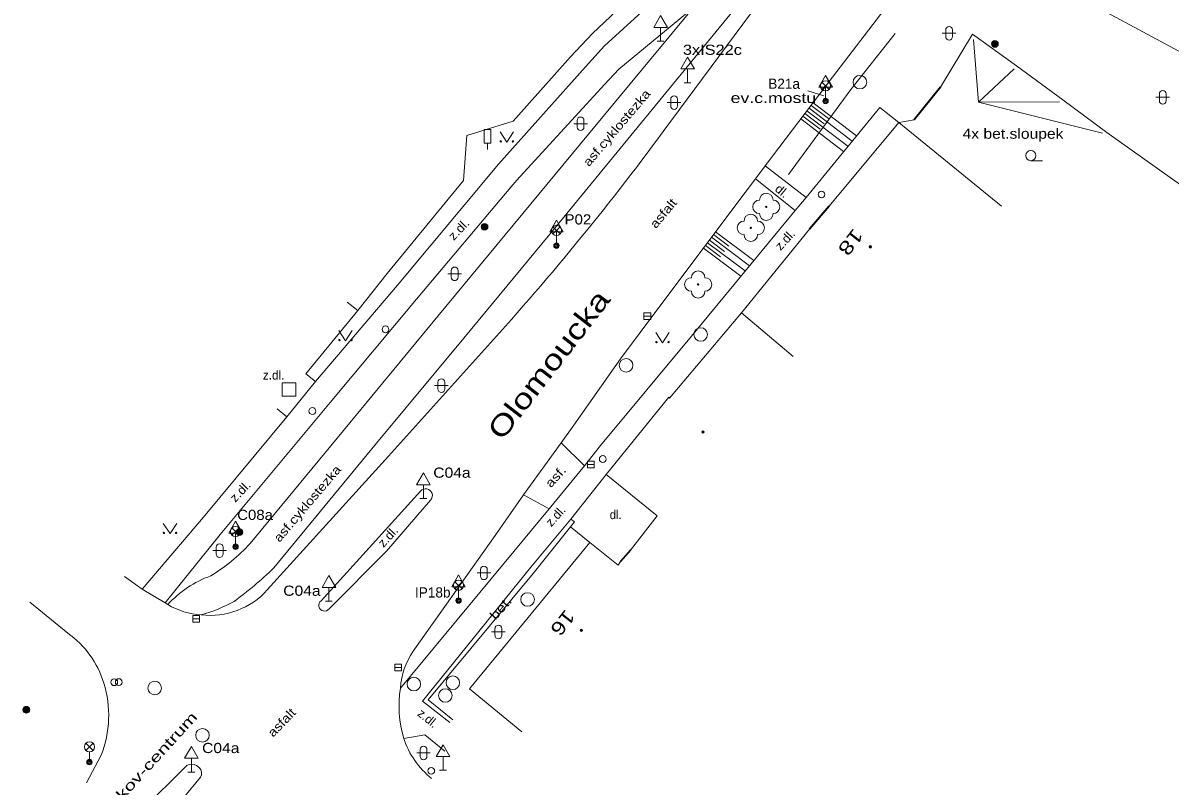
# Model space of a CAD drawing. Extents: x -568501 to -568291, y -1154101 to -1153799.
# Drawn here: x -568486.5 to -568402, y -1153998.8 to -1153942.5 of the extents above; entities that cross this region are included whole.
import ezdxf
from ezdxf.enums import TextEntityAlignment as Align

# ---------------------------------------------------------------- set-up
doc = ezdxf.new("R2010")
doc.units = 0
doc.header["$LTSCALE"] = 0.3
for name, color, linetype, lineweight in [('10', 7, 'Continuous', 13), ('11', 7, 'Continuous', 13), ('12', 7, 'Continuous', 13), ('14', 7, 'Continuous', 13), ('15', 7, 'Continuous', 13), ('22', 7, 'Continuous', 13), ('25', 7, 'Continuous', 13), ('26', 7, 'Continuous', 13), ('27', 7, 'Continuous', 13), ('28', 7, 'Continuous', 13), ('33', 7, 'Continuous', 13), ('34', 7, 'Continuous', 13), ('36', 7, 'Continuous', 13), ('38', 7, 'Continuous', 13), ('39', 7, 'Continuous', 13), ('42', 7, 'Continuous', 13), ('5', 7, 'Continuous', 13), ('6', 7, 'Continuous', 35), ('7', 7, 'Continuous', 13), ('8', 7, 'Continuous', 35)]:
    doc.layers.add(name, color=color, linetype=linetype, lineweight=lineweight)
for name, color, linetype in [('40', 7, 'Continuous'), ('47', 7, 'Continuous'), ('49', 7, 'Continuous')]:
    doc.layers.add(name, color=color, linetype=linetype)

msp = doc.modelspace()

# ---------------------------------------------------------------- linework, layer by layer
at = {"layer": '10'}
for p, q in [((-568459.56, -1153974.44), (-568452.72, -1153966.81)), ((-568468.5, -1153984.3), (-568459.56, -1153974.44)), ((-568464.54, -1153985.09), (-568457.22, -1153977.01)), ((-568457.75, -1153988.82), (-568451.7, -1153980.29)), ((-568486.01, -1153985.2), (-568483.21, -1153987.48)), ((-568481.83, -1153998.51), (-568480.74, -1153996.47)), ((-568478.54, -1154001.31), (-568474.4, -1153997.21)), ((-568473.72, -1153997.23), (-568473.49, -1153997.4)), ((-568477.06, -1154002.51), (-568473.42, -1153998.1))]:
    msp.add_line(p, q, dxfattribs=at)
for points in [[(-568451.7, -1153980.29), (-568449.61, -1153977.28), (-568446.84, -1153973.45), (-568445.91, -1153972.15), (-568442.46, -1153967.27), (-568439.57, -1153963.38), (-568433.28, -1153955), (-568432.53, -1153954), (-568431.81, -1153953.03), (-568426.84, -1153946.5), (-568420.35, -1153937.98), (-568416.07, -1153932.32)], [(-568439.32, -1153950.51), (-568432.9, -1153941.84), (-568427.22, -1153934.12)], [(-568463.95, -1153985.68), (-568459.72, -1153981.43), (-568456.47, -1153977.68)], [(-568479.03, -1153983.31), (-568477.73, -1153984.25), (-568476.04, -1153985.26), (-568475.84, -1153985.38)]]:
    msp.add_lwpolyline(points, dxfattribs=at)
for centre, radius, start, end in [((-568598.8003, -1153833.0615), 198.0609, 317.52333, 323.63038), ((-568456.8362, -1153977.3352), 0.503, 316.72145, 139.7276), ((-568472.7383, -1153980.4472), 5.7278, 263.66789, 317.72758), ((-568472.9663, -1153980.4342), 5.7201, 239.84169, 265.95285), ((-568464.292, -1153985.432), 0.4224, 125.95584, 324.04416), ((-568487.1888, -1153993.1519), 6.9283, 16.6224, 54.95079), ((-568453.3107, -1153991.8779), 5.3906, 145.44041, 176.30001), ((-568488.2162, -1153993.5486), 8.0267, 338.65634, 17.23741), ((-568450.1568, -1153992.8472), 8.6342, 171.22484, 196.15793), ((-568452.5171, -1153993.2846), 6.25, 198.32832, 231.70802), ((-568474.0827, -1153997.9905), 0.8425, 64.50422, 112.12642), ((-568474.0017, -1153997.8047), 0.6524, 333.08275, 38.33843)]:
    msp.add_arc(centre, radius, start, end, dxfattribs=at)
at = {"layer": '11'}
for p, q in [((-568447.22, -1153957.51), (-568433.85, -1153941.21)), ((-568437.12, -1153941.38), (-568442.59, -1153945.91)), ((-568437.12, -1153941.38), (-568442.48, -1153947.86)), ((-568432.53, -1153954), (-568429.61, -1153956.34)), ((-568465.66, -1153968.38), (-568461.83, -1153963.7)), ((-568465.66, -1153968.38), (-568464.95, -1153968.94)), ((-568463.86, -1153970.48), (-568471.98, -1153980.21)), ((-568467.78, -1153970.96), (-568467.05, -1153971.53)), ((-568462.41, -1153971.99), (-568469.77, -1153980.87)), ((-568460.46, -1153973.49), (-568468.03, -1153982.68)), ((-568446.84, -1153973.45), (-568445.13, -1153975.16)), ((-568446.13, -1153979.08), (-568443.53, -1153975.79)), ((-568447.73, -1153978.32), (-568449.61, -1153977.28)), ((-568477.73, -1153984.25), (-568473.21, -1153978.93)), ((-568444.74, -1153980.8), (-568446.162, -1153979.655)), ((-568471.98, -1153980.21), (-568476.04, -1153985.26))]:
    msp.add_line(p, q, dxfattribs=at)
for points in [[(-568451.52, -1153952.97), (-568451.46, -1153952.92), (-568445.04, -1153945.75), (-568443.66, -1153944.18), (-568437.31, -1153938.38), (-568436.1, -1153937.25), (-568432.62, -1153934.09)], [(-568442.59, -1153945.91), (-568443.65, -1153947.05), (-568450.12, -1153954.09), (-568450.55, -1153954.6), (-568457.5, -1153962.87), (-568463.86, -1153970.48)], [(-568462.41, -1153971.99), (-568455.94, -1153964.12), (-568449.09, -1153955.83), (-568442.48, -1153947.86)], [(-568428.8, -1153955.36), (-568423.37, -1153948.74), (-568421.95, -1153949.83)], [(-568464.95, -1153968.94), (-568458.91, -1153961.84), (-568451.46, -1153952.92)], [(-568445.13, -1153975.16), (-568443.94, -1153973.66), (-568437.25, -1153965.59), (-568429.61, -1153956.34), (-568428.8, -1153955.36), (-568431.81, -1153953.03)], [(-568447.22, -1153957.51), (-568454.02, -1153965.74), (-568460.46, -1153973.49)], [(-568473.21, -1153978.93), (-568467.05, -1153971.53), (-568464.95, -1153968.94)], [(-568458.69, -1153991.53), (-568450.34, -1153981.46), (-568447.73, -1153978.32), (-568445.13, -1153975.16)], [(-568455.04, -1153994.08), (-568457.06, -1153992.49), (-568449.07, -1153982.61), (-568446.13, -1153979.08), (-568445.86, -1153979.28)], [(-568445.86, -1153979.28), (-568446.162, -1153979.655), (-568448.92, -1153983.08)], [(-568448.92, -1153983.08), (-568456.65, -1153992.39), (-568454.82, -1153993.866)], [(-568455.41, -1153996.18), (-568456.9, -1153994.97), (-568458.45, -1153995.25)]]:
    msp.add_lwpolyline(points, dxfattribs=at)
for centre, radius, start, end in [((-568987.7107, -1154929.3603), 1154.3916, 58.50566, 59.89077), ((-568598.8116, -1154282.7187), 399.3866, 57.62556, 61.60266), ((-568479.5527, -1153971.9543), 13.236, 301.33199, 317.65447), ((-568469.9419, -1153990.7693), 7.9896, 109.96597, 137.58085), ((-568486.5097, -1153963.7078), 26.4848, 305.97945, 314.24653), ((-568476.5758, -1153974.9538), 11.6365, 285.99146, 298.91164)]:
    msp.add_arc(centre, radius, start, end, dxfattribs=at)
at = {"layer": '12'}
msp.add_arc((-568645.0661, -1154364.1594), 495.3805, 58.1384, 61.39848, dxfattribs=at)
at = {"layer": '14'}
msp.add_lwpolyline([(-568415.48, -1153937.58), (-568406.64, -1153941.73), (-568392.63, -1153949.25), (-568382.59, -1153955.78), (-568371.09, -1153963.05), (-568356.19, -1153973.32)], dxfattribs=at)
at = {"layer": '15'}
for p, q in [((-568428.428, -1153948.586), (-568427.151, -1153949.557)), ((-568428.276, -1153948.387), (-568425.077, -1153950.821)), ((-568429.033, -1153949.382), (-568427.768, -1153950.344)), ((-568428.882, -1153949.183), (-568425.712, -1153951.595)), ((-568428.73, -1153948.984), (-568427.46, -1153949.951)), ((-568428.579, -1153948.785), (-568425.395, -1153951.208)), ((-568429.185, -1153949.58), (-568426.029, -1153951.982)), ((-568435.46, -1153957.905), (-568432.647, -1153960.017)), ((-568436.061, -1153958.705), (-568433.284, -1153960.788)), ((-568435.911, -1153958.505), (-568434.796, -1153959.341)), ((-568435.76, -1153958.305), (-568432.965, -1153960.403)), ((-568435.61, -1153958.105), (-568434.489, -1153958.947)), ((-568436.361, -1153959.104), (-568433.603, -1153961.174)), ((-568436.211, -1153958.904), (-568435.104, -1153959.735))]:
    msp.add_line(p, q, dxfattribs=at)
at = {"layer": '22'}
for centre in [(-568431.73, -1153956.06), (-568432.87, -1153957.61), (-568436.75, -1153961.78)]:
    msp.add_circle(centre, 0.05, dxfattribs=at)
for centre, start, end in [((-568431.73, -1153955.56), 0, 180), ((-568432.23, -1153956.06), 90, 270), ((-568431.23, -1153956.06), 270, 90), ((-568433.37, -1153957.61), 90, 270), ((-568432.87, -1153957.11), 0, 180), ((-568432.37, -1153957.61), 270, 90), ((-568431.73, -1153956.56), 180, 0), ((-568432.87, -1153958.11), 180, 0), ((-568437.25, -1153961.78), 90, 270), ((-568436.75, -1153961.28), 0, 180), ((-568436.25, -1153961.78), 270, 90), ((-568436.75, -1153962.28), 180, 0)]:
    msp.add_arc(centre, 0.5, start, end, dxfattribs=at)
at = {"layer": '25'}
for centre, radius in [((-568414.88, -1153944.05), 0.25), ((-568414.88, -1153944.05), 0.2), ((-568414.88, -1153944.05), 0.15), ((-568414.88, -1153944.05), 0.1), ((-568414.88, -1153944.05), 0.05), ((-568452.49, -1153957.53), 0.25), ((-568452.49, -1153957.53), 0.2), ((-568452.49, -1153957.53), 0.15), ((-568452.49, -1153957.53), 0.1), ((-568452.49, -1153957.53), 0.05), ((-568470.55, -1153980.04), 0.25), ((-568470.55, -1153980.04), 0.2), ((-568470.55, -1153980.04), 0.15), ((-568470.55, -1153980.04), 0.1), ((-568470.55, -1153980.04), 0.05), ((-568486.26, -1153993.13), 0.25), ((-568486.26, -1153993.13), 0.2), ((-568486.26, -1153993.13), 0.15), ((-568486.26, -1153993.13), 0.1), ((-568486.26, -1153993.13), 0.05)]:
    msp.add_circle(centre, radius, dxfattribs=at)
at = {"layer": '26'}
msp.add_lwpolyline([(-568467.4, -1153970.02), (-568466.4, -1153970.02), (-568466.4, -1153969.02), (-568467.4, -1153969.02)], close=True, dxfattribs=at)
at = {"layer": '27'}
for p, q in [((-568440.74, -1153964.12), (-568440.24, -1153964.12)), ((-568444.91, -1153975.05), (-568444.41, -1153975.05)), ((-568474, -1153986.43), (-568473.5, -1153986.43)), ((-568459.1, -1153990.02), (-568458.6, -1153990.02))]:
    msp.add_line(p, q, dxfattribs=at)
for points in [[(-568440.74, -1153964.37), (-568440.24, -1153964.37), (-568440.24, -1153963.87), (-568440.74, -1153963.87)], [(-568444.91, -1153975.3), (-568444.41, -1153975.3), (-568444.41, -1153974.8), (-568444.91, -1153974.8)], [(-568474, -1153986.68), (-568473.5, -1153986.68), (-568473.5, -1153986.18), (-568474, -1153986.18)], [(-568459.1, -1153990.27), (-568458.6, -1153990.27), (-568458.6, -1153989.77), (-568459.1, -1153989.77)]]:
    msp.add_lwpolyline(points, close=True, dxfattribs=at)
for centre in [(-568424.83, -1153946.87), (-568436.56, -1153965.47), (-568442.06, -1153967.74), (-568449.32, -1153985), (-568457.7, -1153991.24), (-568454.83, -1153991.14), (-568476.8, -1153991.53), (-568455.38, -1153992.08), (-568473.28, -1153995.01)]:
    msp.add_circle(centre, 0.5, dxfattribs=at)
at = {"layer": '28'}
for centre in [(-568427.66, -1153955.15), (-568459.79, -1153965.09), (-568465.18, -1153971.11), (-568443.78, -1153974.65), (-568479.78, -1153991.1), (-568479.45, -1153991.09), (-568456.42, -1153997.63)]:
    msp.add_circle(centre, 0.25, dxfattribs=at)
at = {"layer": '33'}
for p, q in [((-568427.625, -1153947.4), (-568427.095, -1153946.87)), ((-568427.625, -1153946.87), (-568427.095, -1153947.4)), ((-568427.36, -1153947.51), (-568427.36, -1153948.26)), ((-568447.455, -1153958.06), (-568446.925, -1153957.53)), ((-568447.455, -1153957.53), (-568446.925, -1153958.06)), ((-568447.19, -1153958.17), (-568447.19, -1153958.92)), ((-568471.105, -1153980.26), (-568470.575, -1153979.73)), ((-568471.105, -1153979.73), (-568470.575, -1153980.26)), ((-568470.84, -1153980.37), (-568470.84, -1153981.12)), ((-568454.675, -1153984.22), (-568454.145, -1153983.69)), ((-568454.675, -1153983.69), (-568454.145, -1153984.22)), ((-568454.41, -1153984.33), (-568454.41, -1153985.08)), ((-568481.875, -1153996.13), (-568481.345, -1153995.6)), ((-568481.875, -1153995.6), (-568481.345, -1153996.13)), ((-568481.61, -1153996.24), (-568481.61, -1153996.99))]:
    msp.add_line(p, q, dxfattribs=at)
for centre, radius in [((-568427.36, -1153947.135), 0.375), ((-568427.36, -1153948.26), 0.2), ((-568427.36, -1153948.26), 0.1445), ((-568427.36, -1153948.26), 0.0876), ((-568447.19, -1153957.795), 0.375), ((-568447.19, -1153958.92), 0.2), ((-568447.19, -1153958.92), 0.1445), ((-568447.19, -1153958.92), 0.0876), ((-568470.84, -1153979.995), 0.375), ((-568470.84, -1153981.12), 0.2), ((-568470.84, -1153981.12), 0.1445), ((-568470.84, -1153981.12), 0.0876), ((-568454.41, -1153983.955), 0.375), ((-568454.41, -1153985.08), 0.2), ((-568454.41, -1153985.08), 0.1445), ((-568454.41, -1153985.08), 0.0876), ((-568481.61, -1153995.865), 0.375), ((-568481.61, -1153996.99), 0.2), ((-568481.61, -1153996.99), 0.1445), ((-568481.61, -1153996.99), 0.0876)]:
    msp.add_circle(centre, radius, dxfattribs=at)
at = {"layer": '34'}
for p, q in [((-568439.52, -1153942.832), (-568439.52, -1153943.85)), ((-568439.77, -1153943.85), (-568439.27, -1153943.85)), ((-568437.53, -1153945.892), (-568437.53, -1153946.91)), ((-568437.78, -1153946.91), (-568437.28, -1153946.91)), ((-568427.36, -1153947.242), (-568427.36, -1153948.26)), ((-568447.19, -1153957.902), (-568447.19, -1153958.92)), ((-568457, -1153976.542), (-568457, -1153977.56)), ((-568457.25, -1153977.56), (-568456.75, -1153977.56)), ((-568470.84, -1153980.102), (-568470.84, -1153981.12)), ((-568463.96, -1153984.112), (-568463.96, -1153985.13)), ((-568454.41, -1153984.062), (-568454.41, -1153985.08)), ((-568464.21, -1153985.13), (-568463.71, -1153985.13)), ((-568474.1, -1153996.702), (-568474.1, -1153997.72)), ((-568455.55, -1153996.572), (-568455.55, -1153997.59)), ((-568455.8, -1153997.59), (-568455.3, -1153997.59)), ((-568474.35, -1153997.72), (-568473.85, -1153997.72))]:
    msp.add_line(p, q, dxfattribs=at)
for points in [[(-568440.02, -1153942.832), (-568439.02, -1153942.832), (-568439.52, -1153941.966)], [(-568438.03, -1153945.892), (-568437.03, -1153945.892), (-568437.53, -1153945.026)], [(-568427.86, -1153947.242), (-568426.86, -1153947.242), (-568427.36, -1153946.376)], [(-568447.69, -1153957.902), (-568446.69, -1153957.902), (-568447.19, -1153957.036)], [(-568457.5, -1153976.542), (-568456.5, -1153976.542), (-568457, -1153975.676)], [(-568471.34, -1153980.102), (-568470.34, -1153980.102), (-568470.84, -1153979.236)], [(-568464.46, -1153984.112), (-568463.46, -1153984.112), (-568463.96, -1153983.246)], [(-568454.91, -1153984.062), (-568453.91, -1153984.062), (-568454.41, -1153983.196)], [(-568474.6, -1153996.702), (-568473.6, -1153996.702), (-568474.1, -1153995.836)], [(-568456.05, -1153996.572), (-568455.05, -1153996.572), (-568455.55, -1153995.706)]]:
    msp.add_lwpolyline(points, close=True, dxfattribs=at)
at = {"layer": '36'}
for p, q in [((-568418.758, -1153943.261), (-568417.758, -1153943.261)), ((-568418.508, -1153943.011), (-568418.508, -1153943.511)), ((-568418.008, -1153943.011), (-568418.008, -1153943.511)), ((-568402.759, -1153947.733), (-568402.759, -1153948.233)), ((-568402.259, -1153947.733), (-568402.259, -1153948.233)), ((-568439.024, -1153948.371), (-568438.024, -1153948.371)), ((-568438.774, -1153948.121), (-568438.774, -1153948.621)), ((-568438.274, -1153948.121), (-568438.274, -1153948.621)), ((-568403.009, -1153947.983), (-568402.009, -1153947.983)), ((-568445.914, -1153949.936), (-568444.914, -1153949.936)), ((-568445.664, -1153949.686), (-568445.664, -1153950.186)), ((-568445.164, -1153949.686), (-568445.164, -1153950.186)), ((-568412.237, -1153952.658), (-568411.362, -1153952.658)), ((-568455.194, -1153960.997), (-568454.194, -1153960.997)), ((-568454.944, -1153960.747), (-568454.944, -1153961.247)), ((-568454.444, -1153960.747), (-568454.444, -1153961.247)), ((-568456.173, -1153969.235), (-568455.173, -1153969.235)), ((-568455.923, -1153968.985), (-568455.923, -1153969.485)), ((-568455.423, -1153968.985), (-568455.423, -1153969.485)), ((-568472.514, -1153981.398), (-568471.514, -1153981.398)), ((-568472.264, -1153981.148), (-568472.264, -1153981.648)), ((-568471.764, -1153981.148), (-568471.764, -1153981.648)), ((-568453.039, -1153983.04), (-568452.039, -1153983.04)), ((-568452.789, -1153982.79), (-568452.789, -1153983.29)), ((-568452.289, -1153982.79), (-568452.289, -1153983.29)), ((-568451.971, -1153987.394), (-568450.971, -1153987.394)), ((-568451.721, -1153987.144), (-568451.721, -1153987.644)), ((-568451.221, -1153987.144), (-568451.221, -1153987.644)), ((-568457.487, -1153996.313), (-568456.487, -1153996.313)), ((-568457.237, -1153996.063), (-568457.237, -1153996.563)), ((-568456.737, -1153996.063), (-568456.737, -1153996.563))]:
    msp.add_line(p, q, dxfattribs=at)
for points in [[(-568451.35, -1153950.532), (-568450.85, -1153951.282), (-568450.35, -1153950.532)], [(-568463.237, -1153965.178), (-568462.737, -1153965.928), (-568462.237, -1153965.178)], [(-568439.878, -1153965.327), (-568439.378, -1153966.077), (-568438.878, -1153965.327)], [(-568476.172, -1153979.393), (-568475.672, -1153980.143), (-568475.172, -1153979.393)]]:
    msp.add_lwpolyline(points, dxfattribs=at)
for centre, radius in [((-568451.3006, -1153951.2321), 0.05), ((-568450.4012, -1153951.2321), 0.05), ((-568412.2367, -1153952.2829), 0.375), ((-568463.1878, -1153965.8784), 0.05), ((-568462.2884, -1153965.8784), 0.05), ((-568439.8285, -1153966.0273), 0.05), ((-568438.9291, -1153966.0273), 0.05), ((-568476.1232, -1153980.0934), 0.05), ((-568475.2238, -1153980.0934), 0.05)]:
    msp.add_circle(centre, radius, dxfattribs=at)
for centre, start, end in [((-568418.2572, -1153943.013), 0, 180), ((-568418.2572, -1153943.513), 180, 0), ((-568402.5083, -1153947.7337), 0, 180), ((-568438.5235, -1153948.1214), 0, 180), ((-568438.5235, -1153948.6214), 180, 0), ((-568402.5083, -1153948.2337), 180, 0), ((-568445.4139, -1153949.6868), 0, 180), ((-568445.4139, -1153950.1868), 180, 0), ((-568454.6934, -1153960.7477), 0, 180), ((-568454.6934, -1153961.2477), 180, 0), ((-568455.6725, -1153968.9857), 0, 180), ((-568455.6725, -1153969.4857), 180, 0), ((-568472.0136, -1153981.1489), 0, 180), ((-568472.0136, -1153981.6489), 180, 0), ((-568452.5384, -1153982.7905), 0, 180), ((-568452.5384, -1153983.2905), 180, 0), ((-568451.4705, -1153987.1447), 0, 180), ((-568451.4705, -1153987.6447), 180, 0), ((-568456.9863, -1153996.0637), 0, 180), ((-568456.9863, -1153996.5637), 180, 0)]:
    msp.add_arc(centre, 0.25, start, end, dxfattribs=at)
at = {"layer": '38'}
msp.add_line((-568452.28, -1153951.355), (-568452.28, -1153951.84), dxfattribs=at)
msp.add_lwpolyline([(-568452.53, -1153951.355), (-568452.03, -1153951.355), (-568452.03, -1153950.355), (-568452.53, -1153950.355)], close=True, dxfattribs=at)
at = {"layer": '39'}
for centre, radius in [((-568424.0604, -1153959.0083), 0.09), ((-568424.0604, -1153959.0083), 0.0398), ((-568436.3997, -1153972.6525), 0.09), ((-568436.3997, -1153972.6525), 0.0398), ((-568445.3578, -1153987.2827), 0.09), ((-568445.3578, -1153987.2827), 0.0398)]:
    msp.add_circle(centre, radius, dxfattribs=at)
at = {"layer": '42'}
for p, q in [((-568427.49, -1153947.866), (-568428.676, -1153947.507)), ((-568416.092, -1153948.348), (-568410.123, -1153948.318)), ((-568416.092, -1153948.348), (-568406.958, -1153950.624))]:
    msp.add_line(p, q, dxfattribs=at)
msp.add_lwpolyline([(-568416.452, -1153943.733), (-568416.092, -1153948.348), (-568413.464, -1153945.886)], dxfattribs=at)
at = {"layer": '5'}
for p, q in [((-568438.858, -1153970.15), (-568433.56, -1153963.86)), ((-568438.92, -1153970.1), (-568443.53, -1153975.79)), ((-568438.858, -1153970.15), (-568438.92, -1153970.1)), ((-568449.749, -1153994.757), (-568453.61, -1153991.58))]:
    msp.add_line(p, q, dxfattribs=at)
for points in [[(-568429.736, -1153967.081), (-568433.56, -1153963.86), (-568428.54, -1153957.71), (-568427.1, -1153956.02), (-568421.95, -1153949.83), (-568414.4, -1153956.01)], [(-568442.47, -1153982.21), (-568441.73, -1153981.37), (-568439.758, -1153978.846), (-568443.53, -1153975.79)], [(-568453.61, -1153991.58), (-568444.74, -1153980.8), (-568442.64, -1153982.47), (-568442.47, -1153982.21)]]:
    msp.add_lwpolyline(points, dxfattribs=at)
at = {"layer": '6'}
for p, q in [((-568427.1, -1153956.02), (-568428.54, -1153957.71)), ((-568441.73, -1153981.37), (-568442.47, -1153982.21))]:
    msp.add_line(p, q, dxfattribs=at)
at = {"layer": '7'}
for p, q in [((-568421.95, -1153949.83), (-568420.82, -1153949.64)), ((-568462.615, -1153963.08), (-568461.83, -1153963.7))]:
    msp.add_line(p, q, dxfattribs=at)
for points in [[(-568437.06, -1153936.21), (-568444.53, -1153943.27), (-568446.16, -1153945), (-568450.39, -1153949.74)], [(-568430.1, -1153953.68), (-568425.5, -1153947.42), (-568422.23, -1153943.29)], [(-568418.88, -1153947.23), (-568416.54, -1153943.33), (-568413.3, -1153945.67), (-568409.87, -1153948.17), (-568406.63, -1153950.58), (-568397.3, -1153957.22)], [(-568450.39, -1153949.74), (-568453.8, -1153950.8), (-568454.03, -1153954.12), (-568459.68, -1153960.98), (-568461.83, -1153963.7)]]:
    msp.add_lwpolyline(points, dxfattribs=at)
at = {"layer": '8'}
msp.add_line((-568418.88, -1153947.23), (-568420.82, -1153949.64), dxfattribs=at)

# ---------------------------------------------------------------- texts
at = {"layer": '40'}
for s, rotation, width, p in [('asf.cyklostezka', 49.573, 1.2, (-568444.796, -1153953.138)), ('dl.', 320.655, 1.05, (-568431.151, -1153954.838)), ('asfalt', 50.073, 1.2, (-568439.866, -1153957.702)), ('z.dl.', 46.41, 1.1, (-568454.761, -1153958.58)), ('z.dl.', 47.739, 1.05, (-568430.67, -1153959.322)), ('asf.cyklostezka', 49.573, 1.2, (-568467.598, -1153980.833)), ('asf.', 47.739, 1.25, (-568447.599, -1153976.811)), ('z.dl.', 46.41, 1.1, (-568470.865, -1153977.883)), ('z.dl.', 47.739, 1.05, (-568447.578, -1153979.684)), ('z.dl.', 47.739, 1.05, (-568459.934, -1153981.203)), ('bet.', 47.739, 1.3, (-568451.689, -1153986.549)), ('asfalt', 46.142, 1.2, (-568468.071, -1153995.195))]:
    msp.add_text(s, height=0.65, rotation=rotation, dxfattribs=dict(at, width=width)).set_placement(p)
msp.add_text('z.dl.', height=0.65, dxfattribs=at).set_placement((-568468.831, -1153968.788))
at = {"layer": '40', "width": 0.95}
msp.add_text('dl.', height=0.65, dxfattribs=at).set_placement((-568443.266, -1153979.076))
at = {"layer": '40'}
msp.add_text('z.dl.', height=0.65, rotation=321.052, dxfattribs=at).set_placement((-568457.492, -1153993.512))
at = {"layer": '42'}
for s, width, p in [('3xIS22c', 1.2, (-568435.6995, -1153944.854)), ('ev.c.mostu', 1.3, (-568431.204, -1153948.406)), ('4x bet.sloupek', 1.15, (-568413.544, -1153951.039)), ('P02', 1.1, (-568445.6115, -1153957.358)), ('C04a', 1.15, (-568454.894, -1153976.027)), ('C08a', 1.1, (-568469.403, -1153979.138)), ('C04a', 1.15, (-568465.951, -1153984.73)), ('C04a', 1.15, (-568471.931, -1153996.324))]:
    msp.add_text(s, height=0.75, dxfattribs=dict(at, width=width)).set_placement(p, align=Align.CENTER)
for s, p in [('B21a', (-568430.414, -1153947.358)), ('IP18b', (-568456.308, -1153984.857))]:
    msp.add_text(s, height=0.75, dxfattribs=at).set_placement(p, align=Align.CENTER)
at = {"layer": '42', "width": 1.5}
msp.add_text('smer Vyskov-centrum', height=0.75, rotation=47.66, dxfattribs=at).set_placement((-568478.4922, -1153999.0901), align=Align.CENTER)
at = {"layer": '47'}
for s, rotation, width, p in [('18', 232.348, 1.35, (-568425.284, -1153957.568)), ('16', 231.636, 1.3, (-568446.512, -1153985.656))]:
    msp.add_text(s, height=1, rotation=rotation, dxfattribs=dict(at, width=width)).set_placement(p)
at = {"layer": '49', "width": 1.3}
msp.add_text('Olomoucka', height=1.5, rotation=52.355, dxfattribs=at).set_placement((-568451.195, -1153973.362))

doc.saveas('drawing.dxf')
